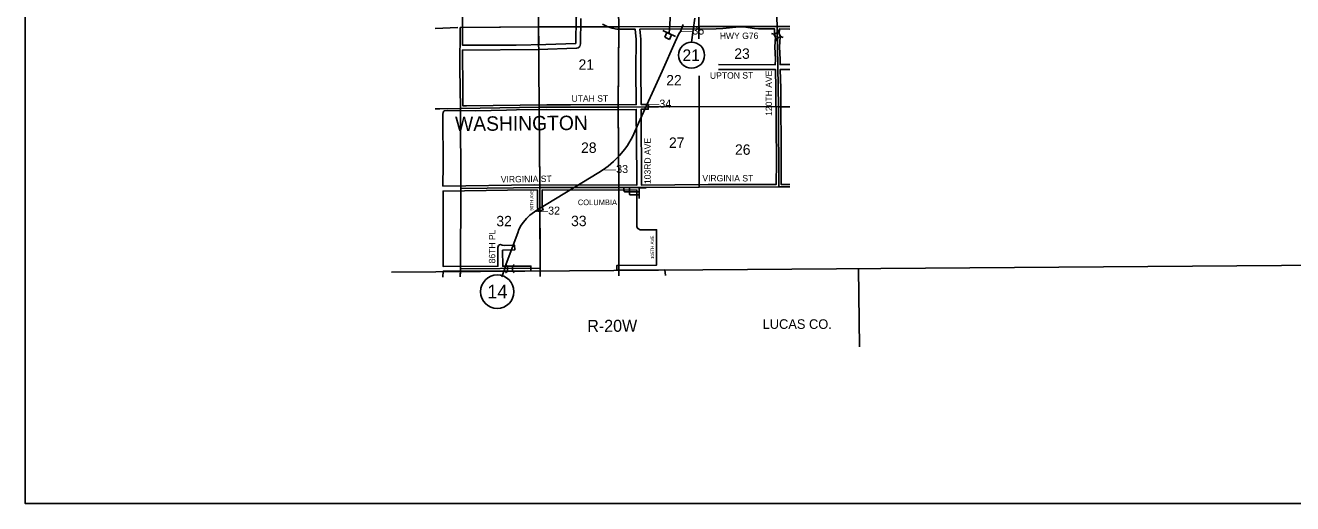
# Model space of a CAD drawing. Extents: x 10133 to 81668, y 5524 to 11018.
# Drawn here: x 20933 to 22912, y 7924 to 8671 of the extents above; entities that cross this region are included whole.
import ezdxf

# ---------------------------------------------------------------- set-up
doc = ezdxf.new("R2010")
doc.units = 0
for name, color, linetype in [('Default', 7, 'Continuous'), ('DisBoundDim', 7, 'Continuous'), ('DisCLMLOR', 7, 'Continuous'), ('DisCLMLSUR', 7, 'Continuous'), ('Level 3', 7, 'Continuous'), ('trf_SignNumber_Text', 7, 'Continuous')]:
    doc.layers.add(name, color=color, linetype=linetype)

msp = doc.modelspace()

# ---------------------------------------------------------------- linework, layer by layer
at = {"layer": 'Default'}
for p, q in [((22101.6, 8656.8), (22097.9, 8658)), ((22105.1, 8649.7), (22103.8, 8646)), ((22108.7, 8660.2), (22109.9, 8663.9)), ((22112.1, 8653.2), (22115.8, 8651.9)), ((21685.4, 8294.7), (21682.7, 8297.5)), ((21693.2, 8294.7), (21696, 8297.5)), ((21685.4, 8286.9), (21682.6, 8284.1)), ((21693.2, 8286.9), (21696, 8284.1))]:
    msp.add_line(p, q, dxfattribs=at)
for points in [[(21856.9, 8794.1), (21859.4, 8668.6)], [(21983.3, 8794.2), (21984.3, 8668.9)], [(22104.3, 8794), (22104.7, 8726.1), (22106.4, 8668.8)], [(21698.9, 8639.9), (21745.3, 8640.6), (21792.2, 8642.4), (21792.6, 8682.9), (21794, 8686.2), (21798.4, 8692.5), (21801.6, 8699.9), (21805.1, 8704.1), (21799.1, 8711.3), (21792.5, 8716.8), (21781.2, 8723.2), (21774.3, 8726.2), (21765.7, 8727.6), (21737.2, 8727.7), (21657.2, 8725.6), (21615.2, 8725.3), (21615.3, 8639.5), (21698.9, 8639.9)], [(21733.8, 8727.7), (21734.1, 8668.6)], [(21800, 8681.3), (21799.6, 8641.7), (21798.5, 8637.8), (21795.6, 8635.4), (21793.4, 8634.9), (21733.5, 8632.8), (21615.2, 8632), (21615.5, 8569.3), (21616, 8544.8), (21621.7, 8544.8)], [(21621.7, 8544.8), (21746.8, 8546.8), (21783.9, 8546.5), (21886.6, 8547), (21886.1, 8601.6), (21886.4, 8648.8), (21884.7, 8664.9), (21856.3, 8664.9), (21848.7, 8666.2), (21841.2, 8668.7), (21833.8, 8672.7)], [(21676.7, 8278.3), (21680.8, 8289.7), (21683.6, 8298.4), (21701.4, 8346.8), (21703.4, 8351.8), (21707.1, 8358.5), (21710.3, 8363.3), (21715.1, 8369.2), (21720.5, 8374.5), (21723.8, 8377.1), (21731.5, 8382.2), (21789.6, 8417.6), (21828, 8441), (21835.3, 8445.6), (21842.6, 8450.8), (21851.2, 8458), (21860.6, 8467.6), (21868.9, 8477.5), (21873, 8483.3), (21880.5, 8496.5), (21890.3, 8517.9), (21927, 8599.3), (21947.5, 8644.7), (21953.3, 8657.7), (21955.6, 8661.3), (21959.7, 8671.9)], [(21859.4, 8668.6), (21984.3, 8668.9)], [(21984.3, 8668.9), (22106.4, 8668.8)], [(21984.3, 8668.9), (21984.4, 8650.2)], [(22106.4, 8668.8), (22126.2, 8668.7)], [(22106.4, 8668.8), (22108.7, 8543.5)], [(21572.3, 8665.9), (21607.8, 8667.2)], [(21611.6, 8667.3), (21611, 8604.1), (21612.2, 8541)], [(21611.6, 8667.3), (21734.1, 8668.6)], [(21615.3, 8667.4), (21734.1, 8668.6)], [(21734.1, 8668.6), (21792.3, 8668.6)], [(21734.1, 8668.6), (21734.2, 8640.3)], [(21734.1, 8668.6), (21859.4, 8668.6)], [(21734.1, 8668.6), (21734.8, 8542.8)], [(21799.7, 8668.6), (21841.5, 8668.6)], [(21859.4, 8668.6), (21858.4, 8543.2)], [(21859.4, 8664.9), (21858.4, 8547)], [(22014.9, 8609.4), (22103.7, 8609.3), (22103.9, 8617.2), (22102.9, 8637.3), (22103.8, 8652.5), (22102.4, 8656.8), (22102.6, 8665.1), (22077.5, 8665.2), (22071.4, 8665.7), (22054.3, 8668.4), (22047.2, 8668.6), (22021.6, 8665.6), (22011.4, 8665.1), (21892.2, 8664.9), (21893.9, 8649), (21893.6, 8601.6), (21894.1, 8547.2), (21905.5, 8547), (21905.4, 8539.6), (21894, 8539.7), (21894.8, 8421), (21999, 8422.2)], [(21984.4, 8665.1), (21984.4, 8649.7)], [(22126.2, 8664.9), (22110.1, 8665), (22109.9, 8657.4), (22110.9, 8655), (22111.3, 8652.7), (22110.4, 8637.3), (22111.4, 8617.4), (22111.2, 8609.4), (22126.2, 8609.4)], [(21984.6, 8592), (21984.8, 8544)], [(21999, 8422.2), (22105.2, 8422.4), (22105.4, 8457.8), (22104.8, 8572), (22104, 8601.8), (22015, 8601.9)], [(22126.2, 8602), (22124.2, 8602), (22111.5, 8601.9), (22112.3, 8572), (22112.9, 8457.7), (22112.7, 8422.4), (22126.2, 8422.4)], [(21984.6, 8587.1), (21984.8, 8544)], [(21572.3, 8540.3), (21612.2, 8541)], [(21572.3, 8540.3), (21579.6, 8540.4)], [(21584.7, 8419.5), (21727.7, 8421.5), (21887.3, 8421.1), (21887.3, 8434), (21886.5, 8539.5), (21783.9, 8539), (21746.8, 8539.3), (21699.5, 8538.9), (21683.7, 8538.1), (21636.2, 8537.4), (21591.6, 8537.5), (21586.7, 8537), (21584.9, 8534.9), (21584.7, 8531.4), (21585, 8450.1), (21584.7, 8422.8), (21584.7, 8419.5)], [(21612.2, 8541), (21734.8, 8542.8)], [(21612.2, 8541), (21612.7, 8416.2)], [(21612.2, 8537.2), (21612.7, 8419.9)], [(21734.8, 8542.8), (21858.4, 8543.2)], [(21734.8, 8542.8), (21735.8, 8417.6)], [(21734.8, 8539.1), (21735.8, 8421.3)], [(21858.4, 8543.2), (21984.8, 8544)], [(21858.4, 8543.2), (21859.5, 8417.5)], [(21858.4, 8539.5), (21859.4, 8421.3)], [(21905.5, 8543.5), (21984.8, 8544)], [(21984.8, 8544), (22104.9, 8543.5)], [(21984.8, 8544), (21984.9, 8421.9)], [(21984.8, 8544), (22108.7, 8543.5)], [(21984.8, 8544), (21985, 8418.1)], [(22108.7, 8543.5), (22126.2, 8543.5)], [(22108.7, 8543.5), (22109, 8418.6)], [(22112.4, 8543.5), (22126.2, 8543.5)], [(21932.2, 8280), (21931.1, 8289.2), (21911.8, 8288.6), (21856.4, 8288.5), (21856.3, 8296), (21918.1, 8296.3), (21918.4, 8351.6), (21892.9, 8351.4), (21889.2, 8353.3), (21887.4, 8356.4), (21887.5, 8413.6), (21739.6, 8413.9), (21739.7, 8386.8), (21741, 8382.6), (21733.8, 8380.5), (21732.3, 8386.1), (21732.1, 8413.8), (21685.5, 8413.5), (21584.8, 8412), (21584.8, 8294.3), (21670.5, 8294.5), (21670.4, 8323.7), (21671.6, 8327), (21672.8, 8328), (21674.4, 8328.4), (21677, 8327.4), (21680.5, 8327.1), (21696.5, 8327.5), (21696.8, 8320), (21677.9, 8319.7), (21678, 8294.5), (21722, 8294.9), (21722, 8287.4), (21646.9, 8286.7), (21584.8, 8286.8), (21584.7, 8277.7)], [(21612.7, 8416.2), (21611.9, 8290.6)], [(21612.7, 8412.4), (21612, 8294.3)], [(21612.7, 8416.2), (21735.8, 8417.6)], [(21735.8, 8417.6), (21736.4, 8291.4)], [(21735.8, 8417.6), (21859.5, 8417.5)], [(21858.8, 8417.5), (21861.7, 8417.5), (21867.2, 8417.5), (21867.3, 8417.5), (21875.8, 8417.6), (21875.9, 8417.6), (21881.6, 8417.4), (21886.1, 8417.4), (21891.2, 8417.3)], [(21859.5, 8417.5), (21859.4, 8292.3)], [(21859.4, 8413.8), (21859.4, 8296)], [(21859.5, 8417.5), (21985, 8418.1)], [(21867.2, 8417.5), (21867.4, 8412.8), (21867.5, 8412), (21867.7, 8411.4), (21867.8, 8411.2), (21868, 8411.1), (21868.2, 8411), (21868.5, 8411), (21869.6, 8410.9), (21875.9, 8410.9)], [(21875.9, 8410.9), (21875.9, 8417.6)], [(21891.3, 8400.4), (21891.3, 8402.6), (21891.2, 8405), (21891.2, 8406.2), (21891.2, 8408.3), (21891.2, 8410.8), (21891.2, 8411.6), (21891.3, 8415), (21891.2, 8417.3)], [(21891.2, 8417.3), (21892.8, 8417.2), (21901.9, 8417.2)], [(21985, 8418.1), (22109, 8418.6)], [(22109, 8418.6), (22126.2, 8418.6)], [(21891.2, 8406.2), (21877.9, 8406), (21877.4, 8406), (21877, 8406.1), (21876.8, 8406.3), (21876.6, 8406.4), (21876.4, 8406.6), (21876.2, 8406.8), (21876.1, 8407.1), (21876, 8407.5), (21876, 8407.8), (21876, 8408.2), (21875.9, 8410.9)], [(21875.9, 8410.9), (21881.4, 8410.9), (21886.1, 8410.9), (21891.2, 8410.8)], [(21736, 8381.1), (21736.4, 8291.4)], [(23729.2, 8303.6), (23604.3, 8302.7), (23478.3, 8300.8), (23353.1, 8299.4), (23229.4, 8297.8), (23102.4, 8297.6), (21504.2, 8285.2)], [(21611.9, 8290.6), (21611.8, 8278.1)], [(21611.9, 8286.8), (21611.8, 8278.1)], [(21611.9, 8290.6), (21736.4, 8291.4)], [(21676.7, 8278.5), (21677.2, 8279.8), (21680.8, 8289.7), (21681.1, 8290.6), (21681.2, 8290.8), (21681.2, 8290.8)], [(21722, 8291.3), (21736.4, 8291.4)], [(21736.4, 8291.4), (21736.4, 8278.8)], [(21736.4, 8291.4), (21736.4, 8278.8)], [(21859.4, 8292.3), (21859.5, 8279.6)], [(21859.4, 8288.5), (21859.5, 8279.6)], [(22233.9, 8291.1), (22235, 8168.9)]]:
    msp.add_lwpolyline(points, dxfattribs=at)
for points in [[(22105.1, 8649.7), (22101.6, 8656.8), (22108.7, 8660.2), (22112.1, 8653.2)], [(21685.4, 8294.7), (21693.2, 8294.7), (21693.2, 8286.9), (21685.4, 8286.9)]]:
    msp.add_lwpolyline(points, close=True, dxfattribs=at)
msp.add_circle((21669.4, 8254.9), 26.1, dxfattribs=at)
at = {"layer": 'DisBoundDim'}
for p, q in [((21928, 8662.4), (21948.1, 8653.1)), ((21934.5, 8659.4), (21931.1, 8652.2)), ((21931.1, 8652.2), (21938.3, 8648.8)), ((21941.7, 8656.1), (21938.3, 8648.8))]:
    msp.add_line(p, q, dxfattribs=at)
at = {"layer": 'DisCLMLOR'}
for p, q in [((21934.5, 8659.4), (21931.1, 8652.2)), ((21934.5, 8659.4), (21931.1, 8652.2)), ((21934.5, 8659.4), (21931.1, 8652.2)), ((21934.5, 8659.4), (21931.1, 8652.2)), ((21931.1, 8652.2), (21938.3, 8648.8)), ((21931.1, 8652.2), (21938.3, 8648.8)), ((21931.1, 8652.2), (21938.3, 8648.8)), ((21931.1, 8652.2), (21938.3, 8648.8)), ((21941.7, 8656.1), (21934.5, 8659.4)), ((21941.7, 8656.1), (21934.5, 8659.4)), ((21941.7, 8656.1), (21934.5, 8659.4)), ((21941.7, 8656.1), (21934.5, 8659.4)), ((21938.3, 8648.8), (21941.7, 8656.1)), ((21938.3, 8648.8), (21941.7, 8656.1)), ((21938.3, 8648.8), (21941.7, 8656.1)), ((21938.3, 8648.8), (21941.7, 8656.1))]:
    msp.add_line(p, q, dxfattribs=at)
at = {"layer": 'DisCLMLSUR'}
for p, q in [((21939.8, 8688.5), (21938.1, 8657.8)), ((21977.8, 8682.1), (21973, 8644.4))]:
    msp.add_line(p, q, dxfattribs=at)
at = {"layer": 'Level 3'}
msp.add_lwpolyline([(20932.5, 9944), (24067.5, 9944), (24067.5, 7924), (20932.5, 7924)], close=True, dxfattribs=at)
at = {"layer": 'trf_SignNumber_Text'}
msp.add_circle((21973, 8624.1), 20.3, dxfattribs=at)

# ---------------------------------------------------------------- texts
at = {"layer": 'Default'}
for s, height, p in [('‒‒35', 12.5, (21955.6, 8656.3)), ('‒‒35', 12.5, (21955.6, 8656.3)), ('‒‒34', 12.5, (21904, 8542.2)), ('‒‒33', 12.5, (21836.6, 8440.2)), ('‒‒32', 12.5, (21730.3, 8375.2)), ('14', 21.25, (21653.9, 8244.4))]:
    msp.add_text(s, height=height, dxfattribs=at).set_placement(p)
for s, height, rotation, p in [('HWY G76', 10, 0.3882, (22017.1, 8649.1)), ('23', 16.25, 0.0154, (22039.7, 8618.4)), ('21', 16.25, 0.014, (21796.4, 8601.3)), ('22', 16.25, 0.0148, (21933.4, 8576.9)), ('UPTON ST', 10, 0.4748, (22001.7, 8587.2)), ('120TH AVE', 10, 90, (22098.6, 8529.4)), ('UTAH ST', 10, 0.2939, (21785.5, 8551.4)), ('WASHINGTON', 22.5, 0.5148, (21603.7, 8505.6)), ('103RD AVE', 10, 89.8975, (21909.2, 8422.9)), ('27', 16.25, 0.0148, (21937.7, 8479.4)), ('28', 16.25, 0.014, (21800.4, 8471.6)), ('26', 16.25, 0.0154, (22040.8, 8468.6)), ('VIRGINIA ST', 10, 0.7391, (21675.1, 8425.3)), ('VIRGINIA ST', 10, 359.8932, (21989.8, 8427.1)), ('90TH AVE', 5, 90, (21725.7, 8381.5)), ('COLUMBIA', 8.75, 0.0148, (21795.4, 8390)), ('32', 16.25, 0.0132, (21668.1, 8357)), ('33', 16.25, 0.0139, (21784.8, 8357.2)), ('86TH PL', 10, 90, (21666.4, 8299.1)), ('105TH AVE', 5, 90.5222, (21914.4, 8306)), ('R-20W', 18.75, 0.2427, (21810.1, 8192.1)), ('LUCAS CO.', 15, 359.9488, (22083.9, 8196.9))]:
    msp.add_text(s, height=height, rotation=rotation, dxfattribs=at).set_placement(p)
at = {"layer": 'trf_SignNumber_Text'}
msp.add_text('21', height=18.26, dxfattribs=at).set_placement((21958.8, 8614.9))

doc.saveas('drawing.dxf')
